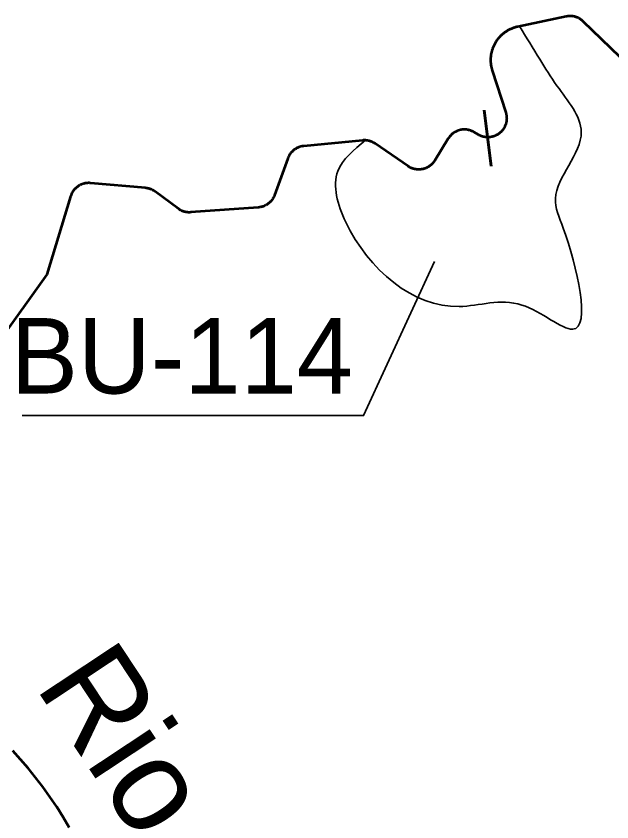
# Model space of a CAD drawing. Extents: x 553962 to 842807, y 8883888 to 9032388.
# Drawn here: x 700588 to 703744, y 8951973 to 8956241 of the extents above; entities that cross this region are included whole.
import ezdxf
from ezdxf.enums import TextEntityAlignment as Align

# ---------------------------------------------------------------- set-up
doc = ezdxf.new("R2010")
doc.units = 0
doc.header["$LTSCALE"] = 150
doc.linetypes.add('MEDIUM_DASHED', pattern=[4.5, 3, -1.5])
for name, color, linetype, lineweight in [('20', 7, 'Continuous', 35), ('24', 7, 'Continuous', 25), ('40', 7, 'Continuous', 60), ('60', 7, 'Continuous', 53)]:
    doc.layers.add(name, color=color, linetype=linetype, lineweight=lineweight)
doc.layers.add('49', color=7, linetype='Continuous')

msp = doc.modelspace()

# ---------------------------------------------------------------- linework, layer by layer
at = {"layer": '20'}
msp.add_line((702471.9, 8955575.6), (702438.6, 8955583.4), dxfattribs=at)
for points in [[(703253.8, 8956186.8), (703243.8, 8956184.8), (703240.1, 8956183.9), (703236.5, 8956183), (703232.8, 8956182.1), (703229.2, 8956181), (703225.5, 8956179.9), (703221.9, 8956178.7), (703218.4, 8956177.4), (703214.8, 8956176), (703211.3, 8956174.6), (703207.8, 8956173.1), (703204.4, 8956171.5), (703201, 8956169.8), (703197.6, 8956168.1), (703194.2, 8956166.3), (703190.9, 8956164.5), (703187.7, 8956162.5), (703184.4, 8956160.5), (703181.2, 8956158.5), (703178.1, 8956156.3), (703175, 8956154.1), (703172, 8956151.8), (703169, 8956149.5), (703166, 8956147.1), (703163.2, 8956144.7), (703160.3, 8956142.2), (703157.5, 8956139.6), (703154.8, 8956137), (703152.1, 8956134.3), (703149.5, 8956131.5), (703146.9, 8956128.7), (703144.4, 8956125.9), (703142, 8956123), (703139.6, 8956120), (703137.3, 8956117), (703135, 8956113.9), (703132.8, 8956110.8), (703130.7, 8956107.7), (703128.7, 8956104.5), (703126.7, 8956101.3), (703124.8, 8956098), (703122.9, 8956094.7), (703121.1, 8956091.3), (703119.4, 8956087.9), (703117.8, 8956084.5), (703116.2, 8956081.1), (703114.7, 8956077.6), (703113.3, 8956074.1), (703112, 8956070.5), (703110.7, 8956066.9), (703109.5, 8956063.3), (703108.4, 8956059.7), (703107.4, 8956056.1), (703106.4, 8956052.4), (703105.5, 8956048.7), (703104.7, 8956045), (703104, 8956041.2), (703103.3, 8956037.5), (703102.8, 8956033.8), (703102.3, 8956030), (703101.9, 8956026.2), (703101.5, 8956022.5), (703101.3, 8956018.7), (703101.1, 8956014.9), (703101, 8956011.1), (703101, 8956007.3), (703101.1, 8956003.5), (703101.2, 8955999.7), (703101.5, 8955995.9), (703101.8, 8955992.1), (703102.2, 8955988.3), (703102.6, 8955984.6), (703103.2, 8955980.8), (703103.8, 8955977.1), (703104.5, 8955973.4), (703105.3, 8955969.7), (703106.1, 8955966), (703107.1, 8955962.3), (703108.1, 8955958.6), (703109.2, 8955955), (703109.7, 8955953.4), (703181.6, 8955730.2), (703182.4, 8955727.5), (703183.2, 8955724.8), (703183.8, 8955722.1), (703184.4, 8955719.3), (703184.9, 8955716.5), (703185.4, 8955713.7), (703185.7, 8955710.9), (703186, 8955708.1), (703186.2, 8955705.3), (703186.3, 8955702.5)], [(703186.3, 8955702.5), (703186.4, 8955699.6), (703186.3, 8955696.8), (703186.2, 8955694), (703186, 8955691.2), (703185.8, 8955688.3), (703185.4, 8955685.5), (703185, 8955682.7), (703184.4, 8955680), (703183.8, 8955677.2), (703183.2, 8955674.5), (703182.4, 8955671.7), (703181.6, 8955669), (703180.7, 8955666.3), (703179.7, 8955663.7), (703178.7, 8955661.1), (703177.5, 8955658.5), (703176.3, 8955655.9), (703175.1, 8955653.4), (703173.7, 8955650.9), (703172.3, 8955648.4), (703170.8, 8955646), (703169.3, 8955643.7), (703167.7, 8955641.3), (703166, 8955639.1), (703164.2, 8955636.8), (703162.4, 8955634.7), (703160.6, 8955632.5), (703158.7, 8955630.5), (703156.7, 8955628.4), (703154.6, 8955626.5), (703152.5, 8955624.6), (703150.4, 8955622.7), (703148.2, 8955621), (703145.9, 8955619.2), (703143.6, 8955617.6), (703141.3, 8955616), (703138.9, 8955614.5), (703136.5, 8955613), (703134, 8955611.7), (703131.5, 8955610.3), (703129, 8955609.1), (703126.4, 8955607.9), (703123.8, 8955606.8), (703121.2, 8955605.8), (703118.5, 8955604.9), (703115.8, 8955604), (703113.1, 8955603.2), (703110.3, 8955602.5), (703107.6, 8955601.8), (703104.8, 8955601.3), (703102, 8955600.8), (703099.2, 8955600.4), (703096.4, 8955600.1), (703093.6, 8955599.8), (703090.8, 8955599.7), (703088, 8955599.6), (703085.1, 8955599.6), (703082.3, 8955599.7), (703079.5, 8955599.8), (703076.7, 8955600.1), (703073.8, 8955600.4), (703071, 8955600.8), (703068.2, 8955601.2), (703065.5, 8955601.8), (703062.7, 8955602.4), (703060, 8955603.1), (703057.3, 8955603.9), (703054.6, 8955604.8), (703051.9, 8955605.7), (703049.3, 8955606.7), (703046.7, 8955607.8), (703044.1, 8955609), (703041.5, 8955610.2), (703039, 8955611.5), (703036.6, 8955612.9), (703034.6, 8955614.1), (703014.4, 8955626.3), (703012, 8955627.7), (703009.5, 8955629.1), (703007, 8955630.4), (703004.4, 8955631.6), (703001.8, 8955632.7), (702999.2, 8955633.8), (702996.6, 8955634.8), (702993.9, 8955635.7), (702991.2, 8955636.6), (702988.5, 8955637.3), (702985.7, 8955638), (702983, 8955638.7), (702980.2, 8955639.2), (702977.4, 8955639.7), (702974.6, 8955640), (702971.8, 8955640.3), (702969, 8955640.6), (702966.1, 8955640.7), (702963.3, 8955640.8), (702960.5, 8955640.7), (702957.7, 8955640.6), (702954.8, 8955640.5), (702952, 8955640.2)], [(702952, 8955640.2), (702949.2, 8955639.9), (702946.4, 8955639.4), (702943.6, 8955638.9), (702940.9, 8955638.4), (702938.1, 8955637.7), (702935.4, 8955637), (702932.7, 8955636.2), (702930, 8955635.3), (702927.3, 8955634.3), (702924.7, 8955633.3), (702922.1, 8955632.2), (702919.5, 8955631), (702917, 8955629.8), (702914.5, 8955628.4), (702912, 8955627), (702909.6, 8955625.6), (702907.2, 8955624), (702904.9, 8955622.4), (702902.6, 8955620.8), (702900.4, 8955619), (702898.2, 8955617.2), (702896, 8955615.4), (702894, 8955613.5), (702891.9, 8955611.5), (702890, 8955609.5), (702888, 8955607.4), (702886.2, 8955605.3), (702884.4, 8955603.1), (702882.7, 8955600.8), (702881, 8955598.6), (702879.4, 8955596.2), (702877.8, 8955593.9), (702877.3, 8955593.1), (702805.8, 8955476.5), (702804.3, 8955474.1), (702802.7, 8955471.7), (702801, 8955469.4), (702799.3, 8955467.2), (702797.6, 8955465), (702795.7, 8955462.8), (702793.8, 8955460.7), (702791.9, 8955458.7), (702789.8, 8955456.7), (702787.8, 8955454.8), (702785.7, 8955452.9), (702783.5, 8955451.1), (702781.3, 8955449.3), (702779, 8955447.7), (702776.7, 8955446), (702774.3, 8955444.5), (702771.9, 8955443), (702769.5, 8955441.6), (702767, 8955440.2), (702764.5, 8955438.9), (702761.9, 8955437.7), (702759.3, 8955436.6), (702756.7, 8955435.6), (702754, 8955434.6), (702751.3, 8955433.7), (702748.7, 8955432.8), (702745.9, 8955432.1), (702743.2, 8955431.4), (702740.4, 8955430.8), (702737.6, 8955430.3), (702734.8, 8955429.8), (702732, 8955429.5), (702729.2, 8955429.2), (702726.4, 8955429), (702723.6, 8955428.8), (702720.8, 8955428.8), (702717.9, 8955428.8), (702715.1, 8955428.9), (702712.3, 8955429.1), (702709.5, 8955429.4), (702706.7, 8955429.8), (702703.9, 8955430.2), (702701.1, 8955430.7), (702698.3, 8955431.3), (702695.6, 8955432), (702692.8, 8955432.7), (702690.1, 8955433.5), (702687.4, 8955434.4), (702684.8, 8955435.4), (702682.2, 8955436.5), (702679.6, 8955437.6), (702677, 8955438.8), (702674.5, 8955440), (702672, 8955441.4), (702669.5, 8955442.8), (702667.1, 8955444.3), (702664.8, 8955445.8), (702664, 8955446.3), (702489.2, 8955566.1), (702486.8, 8955567.7), (702484.4, 8955569.2), (702482, 8955570.6), (702479.5, 8955572), (702477, 8955573.2), (702474.5, 8955574.5), (702471.9, 8955575.6)], [(702471.9, 8955575.6), (702469.2, 8955576.7), (702466.6, 8955577.7), (702463.9, 8955578.6), (702461.2, 8955579.4), (702458.5, 8955580.2), (702455.8, 8955580.9), (702453, 8955581.5), (702450.2, 8955582.1), (702447.4, 8955582.5), (702444.6, 8955582.9), (702441.8, 8955583.2), (702440.3, 8955583.3)]]:
    msp.add_lwpolyline(points, dxfattribs=at)
msp.add_spline([(702438.6, 8955583.4), (702292.5, 8955420.1), (702334, 8955150.5), (702934.9, 8954702.7), (703266.5, 8954710.9), (703535.9, 8954582.4), (703486.2, 8955117.4), (703444.7, 8955275), (703581.5, 8955627.5), (703453, 8955872.2), (703361.8, 8956013.2), (703254.1, 8956187.3)], degree=3, dxfattribs=at)
msp.add_spline([(702438.6, 8955583.4), (702292.5, 8955420.1), (702334, 8955150.5), (702934.9, 8954702.7), (703266.5, 8954710.9), (703535.9, 8954582.4), (703486.2, 8955117.4), (703444.7, 8955275), (703581.5, 8955627.5), (703453, 8955872.2), (703361.8, 8956013.2), (703254.1, 8956187.3)], degree=3, dxfattribs=at)
at = {"layer": '24', "lineweight": 53}
msp.add_lwpolyline([(700869.6, 8951943), (700837.1, 8951997.8), (700802.8, 8952052.4), (700766.9, 8952105.9), (700729.6, 8952157.8), (700691, 8952207.9), (700651.4, 8952256.4), (700611, 8952303.5), (700570.1, 8952349.2)], dxfattribs=at)
at = {"layer": '40'}
msp.add_line((703067.3, 8955744), (703104.1, 8955446.3), dxfattribs=at)
at = {"layer": '40', "lineweight": 35}
msp.add_lwpolyline([(702803.3, 8954941.4), (702428.6, 8954125.2), (700620.8, 8954125.2)], dxfattribs=at)
at = {"layer": '60', "linetype": 'MEDIUM_DASHED'}
msp.add_line((700750.8, 8954871.7), (698954.1, 8952383.9), dxfattribs=at)
at = {"layer": '60'}
for points in [[(703523.4, 8956241.4), (703520.6, 8956241.3), (703517.8, 8956241.3), (703515, 8956241.1), (703512.2, 8956240.8), (703509.3, 8956240.5), (703506.5, 8956240.1), (703503.8, 8956239.6), (703502, 8956239.2), (703243.8, 8956184.8), (703240.1, 8956183.9), (703236.5, 8956183), (703232.8, 8956182.1), (703229.2, 8956181), (703225.5, 8956179.9), (703221.9, 8956178.7), (703218.4, 8956177.4), (703214.8, 8956176), (703211.3, 8956174.6), (703207.8, 8956173.1), (703204.4, 8956171.5), (703201, 8956169.8), (703197.6, 8956168.1), (703194.2, 8956166.3), (703190.9, 8956164.5), (703187.7, 8956162.5), (703184.4, 8956160.5), (703181.2, 8956158.5), (703178.1, 8956156.3), (703175, 8956154.1), (703172, 8956151.8), (703169, 8956149.5), (703166, 8956147.1), (703163.2, 8956144.7), (703160.3, 8956142.2), (703157.5, 8956139.6), (703154.8, 8956137), (703152.1, 8956134.3), (703149.5, 8956131.5), (703146.9, 8956128.7), (703144.4, 8956125.9), (703142, 8956123), (703139.6, 8956120), (703137.3, 8956117), (703135, 8956113.9), (703132.8, 8956110.8), (703130.7, 8956107.7), (703128.7, 8956104.5), (703126.7, 8956101.3), (703124.8, 8956098), (703122.9, 8956094.7), (703121.1, 8956091.3), (703119.4, 8956087.9), (703117.8, 8956084.5), (703116.2, 8956081.1), (703114.7, 8956077.6), (703113.3, 8956074.1), (703112, 8956070.5), (703110.7, 8956066.9), (703109.5, 8956063.3), (703108.4, 8956059.7), (703107.4, 8956056.1), (703106.4, 8956052.4), (703105.5, 8956048.7), (703104.7, 8956045), (703104, 8956041.2), (703103.3, 8956037.5), (703102.8, 8956033.8), (703102.3, 8956030), (703101.9, 8956026.2), (703101.5, 8956022.5), (703101.3, 8956018.7), (703101.1, 8956014.9), (703101, 8956011.1), (703101, 8956007.3), (703101.1, 8956003.5), (703101.2, 8955999.7), (703101.5, 8955995.9), (703101.8, 8955992.1), (703102.2, 8955988.3), (703102.6, 8955984.6), (703103.2, 8955980.8), (703103.8, 8955977.1), (703104.5, 8955973.4), (703105.3, 8955969.7), (703106.1, 8955966), (703107.1, 8955962.3), (703108.1, 8955958.6), (703109.2, 8955955), (703109.7, 8955953.4), (703181.6, 8955730.2), (703182.4, 8955727.5), (703183.2, 8955724.8), (703183.8, 8955722.1), (703184.4, 8955719.3), (703184.9, 8955716.5), (703185.4, 8955713.7), (703185.7, 8955710.9), (703186, 8955708.1), (703186.2, 8955705.3), (703186.3, 8955702.5)], [(703834.4, 8955977.8), (703592.4, 8956213.1), (703590.3, 8956215), (703588.2, 8956216.9), (703586.1, 8956218.7), (703583.8, 8956220.5), (703581.6, 8956222.2), (703579.3, 8956223.8), (703576.9, 8956225.4), (703574.5, 8956226.9), (703572.1, 8956228.3), (703569.6, 8956229.7), (703567.1, 8956231), (703564.5, 8956232.2), (703562, 8956233.3), (703559.3, 8956234.4), (703556.7, 8956235.4), (703554, 8956236.3), (703551.3, 8956237.2), (703548.6, 8956238), (703545.9, 8956238.7), (703543.1, 8956239.3), (703540.3, 8956239.8), (703537.5, 8956240.3), (703534.7, 8956240.7), (703531.9, 8956241), (703529.1, 8956241.2), (703526.3, 8956241.3), (703523.4, 8956241.4)], [(703186.3, 8955702.5), (703186.4, 8955699.6), (703186.3, 8955696.8), (703186.2, 8955694), (703186, 8955691.2), (703185.8, 8955688.3), (703185.4, 8955685.5), (703185, 8955682.7), (703184.4, 8955680), (703183.8, 8955677.2), (703183.2, 8955674.5), (703182.4, 8955671.7), (703181.6, 8955669), (703180.7, 8955666.3), (703179.7, 8955663.7), (703178.7, 8955661.1), (703177.5, 8955658.5), (703176.3, 8955655.9), (703175.1, 8955653.4), (703173.7, 8955650.9), (703172.3, 8955648.4), (703170.8, 8955646), (703169.3, 8955643.7), (703167.7, 8955641.3), (703166, 8955639.1), (703164.2, 8955636.8), (703162.4, 8955634.7), (703160.6, 8955632.5), (703158.7, 8955630.5), (703156.7, 8955628.4), (703154.6, 8955626.5), (703152.5, 8955624.6), (703150.4, 8955622.7), (703148.2, 8955621), (703145.9, 8955619.2), (703143.6, 8955617.6), (703141.3, 8955616), (703138.9, 8955614.5), (703136.5, 8955613), (703134, 8955611.7), (703131.5, 8955610.3), (703129, 8955609.1), (703126.4, 8955607.9), (703123.8, 8955606.8), (703121.2, 8955605.8), (703118.5, 8955604.9), (703115.8, 8955604), (703113.1, 8955603.2), (703110.3, 8955602.5), (703107.6, 8955601.8), (703104.8, 8955601.3), (703102, 8955600.8), (703099.2, 8955600.4), (703096.4, 8955600.1), (703093.6, 8955599.8), (703090.8, 8955599.7), (703088, 8955599.6), (703085.1, 8955599.6), (703082.3, 8955599.7), (703079.5, 8955599.8), (703076.7, 8955600.1), (703073.8, 8955600.4), (703071, 8955600.8), (703068.2, 8955601.2), (703065.5, 8955601.8), (703062.7, 8955602.4), (703060, 8955603.1), (703057.3, 8955603.9), (703054.6, 8955604.8), (703051.9, 8955605.7), (703049.3, 8955606.7), (703046.7, 8955607.8), (703044.1, 8955609), (703041.5, 8955610.2), (703039, 8955611.5), (703036.6, 8955612.9), (703034.6, 8955614.1), (703014.4, 8955626.3), (703012, 8955627.7), (703009.5, 8955629.1), (703007, 8955630.4), (703004.4, 8955631.6), (703001.8, 8955632.7), (702999.2, 8955633.8), (702996.6, 8955634.8), (702993.9, 8955635.7), (702991.2, 8955636.6), (702988.5, 8955637.3), (702985.7, 8955638), (702983, 8955638.7), (702980.2, 8955639.2), (702977.4, 8955639.7), (702974.6, 8955640), (702971.8, 8955640.3), (702969, 8955640.6), (702966.1, 8955640.7), (702963.3, 8955640.8), (702960.5, 8955640.7), (702957.7, 8955640.6), (702954.8, 8955640.5), (702952, 8955640.2)], [(702952, 8955640.2), (702949.2, 8955639.9), (702946.4, 8955639.4), (702943.6, 8955638.9), (702940.9, 8955638.4), (702938.1, 8955637.7), (702935.4, 8955637), (702932.7, 8955636.2), (702930, 8955635.3), (702927.3, 8955634.3), (702924.7, 8955633.3), (702922.1, 8955632.2), (702919.5, 8955631), (702917, 8955629.8), (702914.5, 8955628.4), (702912, 8955627), (702909.6, 8955625.6), (702907.2, 8955624), (702904.9, 8955622.4), (702902.6, 8955620.8), (702900.4, 8955619), (702898.2, 8955617.2), (702896, 8955615.4), (702894, 8955613.5), (702891.9, 8955611.5), (702890, 8955609.5), (702888, 8955607.4), (702886.2, 8955605.3), (702884.4, 8955603.1), (702882.7, 8955600.8), (702881, 8955598.6), (702879.4, 8955596.2), (702877.8, 8955593.9), (702877.3, 8955593.1), (702805.8, 8955476.5), (702804.3, 8955474.1), (702802.7, 8955471.7), (702801, 8955469.4), (702799.3, 8955467.2), (702797.6, 8955465), (702795.7, 8955462.8), (702793.8, 8955460.7), (702791.9, 8955458.7), (702789.8, 8955456.7), (702787.8, 8955454.8), (702785.7, 8955452.9), (702783.5, 8955451.1), (702781.3, 8955449.3), (702779, 8955447.7), (702776.7, 8955446), (702774.3, 8955444.5), (702771.9, 8955443), (702769.5, 8955441.6), (702767, 8955440.2), (702764.5, 8955438.9), (702761.9, 8955437.7), (702759.3, 8955436.6), (702756.7, 8955435.6), (702754, 8955434.6), (702751.3, 8955433.7), (702748.7, 8955432.8), (702745.9, 8955432.1), (702743.2, 8955431.4), (702740.4, 8955430.8), (702737.6, 8955430.3), (702734.8, 8955429.8), (702732, 8955429.5), (702729.2, 8955429.2), (702726.4, 8955429), (702723.6, 8955428.8), (702720.8, 8955428.8), (702717.9, 8955428.8), (702715.1, 8955428.9), (702712.3, 8955429.1), (702709.5, 8955429.4), (702706.7, 8955429.8), (702703.9, 8955430.2), (702701.1, 8955430.7), (702698.3, 8955431.3), (702695.6, 8955432), (702692.8, 8955432.7), (702690.1, 8955433.5), (702687.4, 8955434.4), (702684.8, 8955435.4), (702682.2, 8955436.5), (702679.6, 8955437.6), (702677, 8955438.8), (702674.5, 8955440), (702672, 8955441.4), (702669.5, 8955442.8), (702667.1, 8955444.3), (702664.8, 8955445.8), (702664, 8955446.3), (702489.2, 8955566.1), (702486.8, 8955567.7), (702484.4, 8955569.2), (702482, 8955570.6), (702479.5, 8955572), (702477, 8955573.2), (702474.5, 8955574.5), (702471.9, 8955575.6)], [(702471.9, 8955575.6), (702469.2, 8955576.7), (702466.6, 8955577.7), (702463.9, 8955578.6), (702461.2, 8955579.4), (702458.5, 8955580.2), (702455.8, 8955580.9), (702453, 8955581.5), (702450.2, 8955582.1), (702447.4, 8955582.5), (702444.6, 8955582.9), (702441.8, 8955583.2), (702439, 8955583.4), (702436.2, 8955583.5), (702433.3, 8955583.6), (702430.5, 8955583.6), (702427.7, 8955583.5), (702424.9, 8955583.3), (702423, 8955583.1), (702111.4, 8955553), (702108.6, 8955552.7), (702105.8, 8955552.3), (702103, 8955551.8), (702100.2, 8955551.2), (702097.5, 8955550.6), (702094.8, 8955549.9), (702092, 8955549.1), (702089.3, 8955548.3), (702086.7, 8955547.3), (702084, 8955546.3), (702081.4, 8955545.2), (702078.8, 8955544.1), (702076.3, 8955542.8), (702073.8, 8955541.6), (702071.3, 8955540.2), (702068.9, 8955538.7), (702066.5, 8955537.2), (702064.1, 8955535.6), (702061.8, 8955534), (702059.6, 8955532.3), (702057.4, 8955530.5), (702055.2, 8955528.7), (702053.1, 8955526.8), (702051.1, 8955524.8), (702049.1, 8955522.8), (702047.1, 8955520.8), (702045.3, 8955518.7), (702043.5, 8955516.5), (702041.7, 8955514.3), (702040, 8955512), (702038.4, 8955509.7), (702036.8, 8955507.3), (702035.3, 8955504.9), (702033.9, 8955502.5), (702032.6, 8955500), (702031.3, 8955497.5), (702030.1, 8955494.9), (702028.9, 8955492.3), (702027.9, 8955489.7), (702027, 8955487.5), (701956.8, 8955293.4), (701955.8, 8955290.8), (701954.7, 8955288.2), (701953.6, 8955285.6), (701952.4, 8955283), (701951.1, 8955280.5), (701949.7, 8955278), (701948.3, 8955275.6), (701946.8, 8955273.2), (701945.2, 8955270.8), (701943.6, 8955268.5), (701941.9, 8955266.3), (701940.1, 8955264.1), (701938.3, 8955261.9), (701936.4, 8955259.8), (701934.5, 8955257.7), (701932.5, 8955255.7), (701930.4, 8955253.8), (701928.3, 8955251.9), (701926.1, 8955250.1), (701923.9, 8955248.3), (701921.7, 8955246.6), (701919.4, 8955245), (701917, 8955243.4), (701914.6, 8955241.9), (701912.2, 8955240.5), (701909.7, 8955239.1), (701907.2, 8955237.8), (701904.6, 8955236.6), (701902, 8955235.5), (701899.4, 8955234.4), (701896.8, 8955233.4), (701894.1, 8955232.5), (701891.4, 8955231.6), (701888.7, 8955230.9), (701885.9, 8955230.2), (701883.2, 8955229.6), (701880.4, 8955229), (701877.6, 8955228.6), (701874.8, 8955228.2), (701872, 8955227.9)], [(701872, 8955227.9), (701870, 8955227.7), (701512.9, 8955202), (701510.1, 8955201.8), (701507.2, 8955201.7), (701504.4, 8955201.7), (701501.6, 8955201.8), (701498.8, 8955201.9), (701495.9, 8955202.2), (701493.1, 8955202.5), (701490.3, 8955202.9), (701487.5, 8955203.3), (701484.8, 8955203.9), (701482, 8955204.5), (701479.3, 8955205.2), (701476.6, 8955206), (701473.9, 8955206.9), (701471.2, 8955207.8), (701468.6, 8955208.8), (701465.9, 8955209.9), (701463.4, 8955211.1), (701460.8, 8955212.3), (701458.3, 8955213.6), (701455.8, 8955215), (701453.4, 8955216.5), (701451, 8955218), (701448.7, 8955219.6), (701446.4, 8955221.2), (701446.1, 8955221.4), (701324.5, 8955311.6), (701322.2, 8955313.3), (701319.8, 8955314.9), (701317.5, 8955316.4), (701315, 8955317.8), (701312.6, 8955319.2), (701310.1, 8955320.5), (701307.5, 8955321.8), (701304.9, 8955322.9), (701302.3, 8955324), (701299.7, 8955325.1), (701297, 8955326), (701294.3, 8955326.9), (701291.6, 8955327.7), (701288.9, 8955328.4), (701286.1, 8955329), (701283.4, 8955329.6), (701280.6, 8955330.1), (701277.8, 8955330.5), (701275, 8955330.8), (701273.8, 8955330.9), (700981.4, 8955357), (700978.5, 8955357.2), (700975.7, 8955357.4), (700972.9, 8955357.4), (700970.1, 8955357.4), (700967.2, 8955357.3), (700964.4, 8955357.1), (700961.6, 8955356.8), (700958.8, 8955356.5), (700956, 8955356.1), (700953.2, 8955355.6), (700950.4, 8955355), (700947.7, 8955354.3), (700945, 8955353.6), (700942.2, 8955352.8), (700939.6, 8955351.9), (700936.9, 8955350.9), (700934.3, 8955349.9), (700931.7, 8955348.7), (700929.1, 8955347.6), (700926.6, 8955346.3), (700924.1, 8955345), (700921.6, 8955343.6), (700919.2, 8955342.1), (700916.8, 8955340.5), (700914.5, 8955338.9), (700912.2, 8955337.3), (700910, 8955335.5), (700907.8, 8955333.7), (700905.7, 8955331.9), (700903.6, 8955330), (700901.6, 8955328), (700899.6, 8955326), (700897.7, 8955323.9), (700895.9, 8955321.7), (700894.1, 8955319.5), (700892.3, 8955317.3), (700890.7, 8955315), (700889.1, 8955312.7), (700887.6, 8955310.3), (700886.1, 8955307.9), (700884.7, 8955305.4), (700883.4, 8955302.9), (700882.1, 8955300.4), (700881, 8955297.8), (700879.9, 8955295.2), (700878.8, 8955292.6), (700877.9, 8955289.9), (700877, 8955287.2), (700876.8, 8955286.5), (700750.8, 8954871.7)]]:
    msp.add_lwpolyline(points, dxfattribs=at)

# ---------------------------------------------------------------- texts
at = {"layer": '40'}
msp.add_text('BU-114', height=400, dxfattribs=at).set_placement((700558.5, 8954242))
at = {"layer": '49'}
msp.add_text('Rio Ipanema', height=500, rotation=303.53, dxfattribs=at).set_placement((701731.3, 8951111.3), align=Align.CENTER)

doc.saveas('drawing.dxf')
